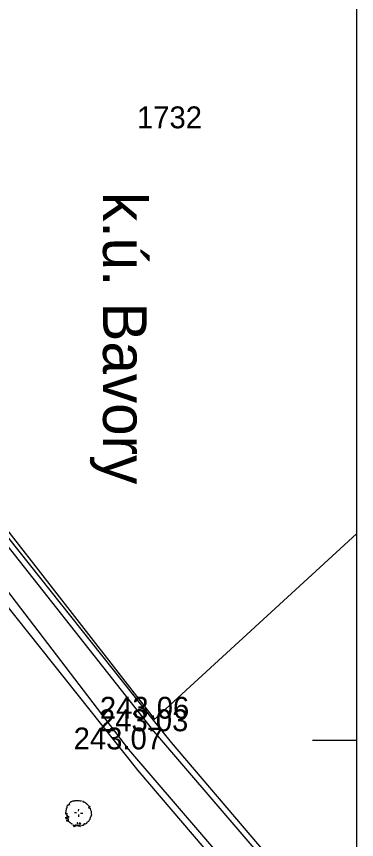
# Model space of a CAD drawing. Extents: x -601739 to -601440, y -1201912 to -1200862.
# Drawn here: x -601473 to -601441.8, y -1201711.4 to -1201636.1 of the extents above; entities that cross this region are included whole.
import ezdxf

# ---------------------------------------------------------------- set-up
doc = ezdxf.new("R2010")
doc.units = 0
for name, color, linetype in [('Hranice parcel', 7, 'Continuous'), ('Parcelní čísla', 7, 'Continuous'), ('u_hrany', 7, 'Continuous'), ('u_popis katastru', 7, 'Continuous'), ('u_vysadba', 7, 'Continuous'), ('u_vyska', 7, 'Continuous'), ('x_rám', 7, 'Continuous')]:
    doc.layers.add(name, color=color, linetype=linetype)

msp = doc.modelspace()

# ---------------------------------------------------------------- linework, layer by layer
at = {"layer": 'Hranice parcel'}
msp.add_line((-601441.842, -1201683.435), (-601460.43, -1201700.48), dxfattribs=at)
for points in [[(-601518.5, -1201574.62), (-601510.22, -1201581.07), (-601510.94, -1201612.53), (-601510.72, -1201619.53), (-601510.05, -1201624.75), (-601508.24, -1201633.75), (-601505.86, -1201640.82), (-601502.47, -1201648.58), (-601498.5, -1201656.04), (-601493.62, -1201663.46), (-601488.75, -1201670.45), (-601479.72, -1201682.69), (-601461.88, -1201705.09), (-601445.87, -1201723.83)], [(-601460.43, -1201700.48), (-601476.54, -1201680.26), (-601485.5, -1201668.12), (-601490.31, -1201661.22), (-601495.06, -1201653.99), (-601498.9, -1201646.76), (-601502.13, -1201639.37), (-601504.35, -1201632.81), (-601505.66, -1201626.3)], [(-601441.842, -1201722.148), (-601442.96, -1201721.08), (-601458.79, -1201702.54), (-601460.43, -1201700.48)]]:
    msp.add_lwpolyline(points, dxfattribs=at)
at = {"layer": 'u_hrany'}
for points in [[(-601460.33, -1201700.35), (-601477.02, -1201679.01), (-601490.59, -1201659.41), (-601493.47, -1201654.35), (-601500.4, -1201641.28), (-601502.56, -1201635.52), (-601504.77, -1201626.02), (-601500.77, -1201618.77)], [(-601443.32, -1201721.42), (-601460.41, -1201701.5), (-601476.94, -1201680.56), (-601485.91, -1201668.41), (-601495.49, -1201654.25), (-601502.92, -1201639.69), (-601504.84, -1201632.93)], [(-601507.17, -1201633.88), (-601501.63, -1201648), (-601497.69, -1201655.55), (-601488, -1201669.96), (-601478.86, -1201682.08), (-601462.72, -1201703.16), (-601444.89, -1201723.91)]]:
    msp.add_lwpolyline(points, dxfattribs=at)
at = {"layer": 'u_vysadba'}
for points in [[(-601468.287, -1201708.283), (-601468.288, -1201708.297), (-601468.334, -1201708.339), (-601468.365, -1201708.366), (-601468.367, -1201708.41), (-601468.369, -1201708.454), (-601468.372, -1201708.512), (-601468.389, -1201708.555), (-601468.405, -1201708.584), (-601468.421, -1201708.612), (-601468.439, -1201708.67), (-601468.441, -1201708.699), (-601468.444, -1201708.758), (-601468.446, -1201708.801), (-601468.448, -1201708.831), (-601468.466, -1201708.903), (-601468.483, -1201708.946), (-601468.485, -1201708.99), (-601468.501, -1201709.018), (-601468.488, -1201709.048), (-601468.445, -1201709.065), (-601468.356, -1201709.04), (-601468.326, -1201709.027), (-601468.359, -1201709.084), (-601468.389, -1201709.112), (-601468.405, -1201709.14), (-601468.408, -1201709.184), (-601468.379, -1201709.186), (-601468.335, -1201709.188), (-601468.322, -1201709.218), (-601468.339, -1201709.261), (-601468.355, -1201709.289), (-601468.357, -1201709.333), (-601468.359, -1201709.377)], [(-601468.287, -1201708.283), (-601468.285, -1201708.253), (-601468.225, -1201708.227), (-601468.195, -1201708.214), (-601468.165, -1201708.201), (-601468.136, -1201708.203), (-601468.107, -1201708.204), (-601468.12, -1201708.174), (-601468.133, -1201708.144), (-601468.116, -1201708.101), (-601468.099, -1201708.058), (-601468.068, -1201708.016), (-601468.037, -1201707.988), (-601468.006, -1201707.961), (-601467.961, -1201707.934), (-601467.917, -1201707.936), (-601467.886, -1201707.908), (-601467.812, -1201707.883), (-601467.753, -1201707.872), (-601467.708, -1201707.859), (-601467.65, -1201707.862), (-601467.605, -1201707.85), (-601467.561, -1201707.852), (-601467.488, -1201707.856), (-601467.415, -1201707.846), (-601467.342, -1201707.849), (-601467.254, -1201707.854), (-601467.166, -1201707.859), (-601467.093, -1201707.863), (-601467.05, -1201707.879), (-601467.022, -1201707.896)], [(-601466.875, -1201707.889), (-601466.891, -1201707.917), (-601466.893, -1201707.946), (-601466.909, -1201707.975), (-601466.864, -1201707.962), (-601466.835, -1201707.964), (-601466.806, -1201707.966), (-601466.763, -1201707.982), (-601466.719, -1201707.985), (-601466.677, -1201708.016), (-601466.649, -1201708.047), (-601466.622, -1201708.092), (-601466.58, -1201708.124), (-601466.524, -1201708.171), (-601466.482, -1201708.217), (-601466.455, -1201708.248), (-601466.414, -1201708.308), (-601466.357, -1201708.341), (-601466.315, -1201708.372), (-601466.272, -1201708.389), (-601466.273, -1201708.418)], [(-601467.471, -1201708.976), (-601467.676, -1201708.965)], [(-601467.304, -1201709.131), (-601467.314, -1201709.335)], [(-601467.287, -1201708.824), (-601467.277, -1201708.62)], [(-601467.121, -1201708.994), (-601466.915, -1201708.99)], [(-601466.273, -1201708.418), (-601466.318, -1201708.431), (-601466.363, -1201708.443), (-601466.379, -1201708.471), (-601466.366, -1201708.501), (-601466.339, -1201708.547), (-601466.309, -1201708.534), (-601466.264, -1201708.521), (-601466.237, -1201708.552), (-601466.223, -1201708.582), (-601466.225, -1201708.611), (-601466.199, -1201708.671), (-601466.187, -1201708.716), (-601466.174, -1201708.76), (-601466.147, -1201708.806), (-601466.149, -1201708.835), (-601466.151, -1201708.879), (-601466.153, -1201708.908), (-601466.141, -1201708.952), (-601466.129, -1201709.012), (-601466.132, -1201709.07), (-601466.121, -1201709.129), (-601466.122, -1201709.158), (-601466.124, -1201709.188), (-601466.126, -1201709.231), (-601466.157, -1201709.259), (-601466.158, -1201709.288), (-601466.175, -1201709.331), (-601466.191, -1201709.36), (-601466.237, -1201709.401), (-601466.241, -1201709.46), (-601466.258, -1201709.517), (-601466.277, -1201709.59), (-601466.324, -1201709.646), (-601466.357, -1201709.717), (-601466.389, -1201709.774), (-601466.449, -1201709.8), (-601466.48, -1201709.828), (-601466.526, -1201709.869), (-601466.557, -1201709.912), (-601466.574, -1201709.955), (-601466.634, -1201709.981), (-601466.679, -1201709.993), (-601466.709, -1201710.006), (-601466.752, -1201709.989), (-601466.795, -1201709.972), (-601466.812, -1201710.015), (-601466.829, -1201710.073), (-601466.846, -1201710.116), (-601466.891, -1201710.128), (-601466.935, -1201710.126)], [(-601468.491, -1201709.37), (-601468.478, -1201709.4), (-601468.465, -1201709.445), (-601468.452, -1201709.475), (-601468.454, -1201709.504), (-601468.425, -1201709.52), (-601468.395, -1201709.492), (-601468.349, -1201709.451), (-601468.378, -1201709.449), (-601468.42, -1201709.418), (-601468.463, -1201709.401)], [(-601468.401, -1201709.609), (-601468.391, -1201709.698), (-601468.347, -1201709.7), (-601468.318, -1201709.701), (-601468.273, -1201709.689), (-601468.331, -1201709.671), (-601468.375, -1201709.669), (-601468.388, -1201709.639)], [(-601468.333, -1201709.437), (-601468.292, -1201709.483), (-601468.25, -1201709.529), (-601468.208, -1201709.561)], [(-601468.208, -1201709.561), (-601468.237, -1201709.559), (-601468.266, -1201709.558), (-601468.296, -1201709.556), (-601468.309, -1201709.526), (-601468.307, -1201709.497), (-601468.32, -1201709.467)], [(-601468.309, -1201709.248), (-601468.311, -1201709.292), (-601468.298, -1201709.322), (-601468.286, -1201709.366), (-601468.273, -1201709.396), (-601468.243, -1201709.398), (-601468.227, -1201709.369), (-601468.167, -1201709.343), (-601468.21, -1201709.326), (-601468.239, -1201709.31), (-601468.296, -1201709.278)], [(-601467.837, -1201710.02), (-601467.88, -1201710.003), (-601467.908, -1201709.987), (-601467.938, -1201709.985), (-601467.964, -1201709.94), (-601467.993, -1201709.924), (-601468.035, -1201709.892), (-601468.078, -1201709.875), (-601468.12, -1201709.829), (-601468.147, -1201709.798), (-601468.219, -1201709.765), (-601468.216, -1201709.721), (-601468.214, -1201709.678), (-601468.227, -1201709.648), (-601468.256, -1201709.631), (-601468.224, -1201709.589), (-601468.195, -1201709.591)], [(-601467.433, -1201709.851), (-601467.422, -1201709.924), (-601467.395, -1201709.97), (-601467.35, -1201709.957), (-601467.349, -1201709.928), (-601467.347, -1201709.899), (-601467.39, -1201709.882), (-601467.419, -1201709.866)], [(-601467.825, -1201710.079), (-601467.729, -1201710.201), (-601467.702, -1201710.246), (-601467.671, -1201710.204), (-601467.669, -1201710.175), (-601467.698, -1201710.159), (-601467.741, -1201710.142), (-601467.769, -1201710.126), (-601467.798, -1201710.11)], [(-601467.603, -1201710.032), (-601467.607, -1201710.105), (-601467.595, -1201710.15), (-601467.567, -1201710.18), (-601467.508, -1201710.169), (-601467.477, -1201710.141), (-601467.49, -1201710.111), (-601467.533, -1201710.094), (-601467.576, -1201710.077)], [(-601467.398, -1201710.028), (-601467.314, -1201710.106), (-601467.286, -1201710.122), (-601467.273, -1201710.152), (-601467.304, -1201710.18), (-601467.333, -1201710.178), (-601467.346, -1201710.148), (-601467.373, -1201710.103), (-601467.4, -1201710.072)], [(-601467.23, -1201709.891), (-601467.204, -1201709.951), (-601467.191, -1201709.995), (-601467.164, -1201710.026), (-601467.134, -1201710.013), (-601467.102, -1201709.971), (-601467.101, -1201709.941), (-601467.144, -1201709.939), (-601467.173, -1201709.923), (-601467.201, -1201709.907), (-601467.231, -1201709.905)], [(-601467.199, -1201710.141), (-601467.188, -1201710.215), (-601467.175, -1201710.245), (-601467.145, -1201710.232), (-601467.114, -1201710.19), (-601467.141, -1201710.159), (-601467.17, -1201710.143), (-601467.199, -1201710.141)], [(-601466.935, -1201710.126), (-601466.979, -1201710.138), (-601467.01, -1201710.166)]]:
    msp.add_lwpolyline(points, dxfattribs=at)
at = {"layer": 'x_rám'}
msp.add_line((-601441.842, -1201702.355), (-601445.882, -1201702.355), dxfattribs=at)
msp.add_lwpolyline([(-601441.842, -1200862.355), (-601441.842, -1201912.355), (-601738.842, -1201912.355), (-601738.842, -1200862.355)], close=True, dxfattribs=at)

# ---------------------------------------------------------------- texts
at = {"layer": 'Parcelní čísla'}
msp.add_text('1732', height=2, dxfattribs=at).set_placement((-601461.943, -1201646.296))
at = {"layer": 'u_popis katastru'}
msp.add_text('k.ú. Bavory', height=4, rotation=270, dxfattribs=at).set_placement((-601465.056, -1201652.136))
at = {"layer": 'u_vyska'}
for s, p in [('243.06', (-601465.34, -1201700.35)), ('243.03', (-601465.425, -1201701.5)), ('243.07', (-601467.74, -1201703.16))]:
    msp.add_text(s, height=2, dxfattribs=at).set_placement(p)

doc.saveas('drawing.dxf')
